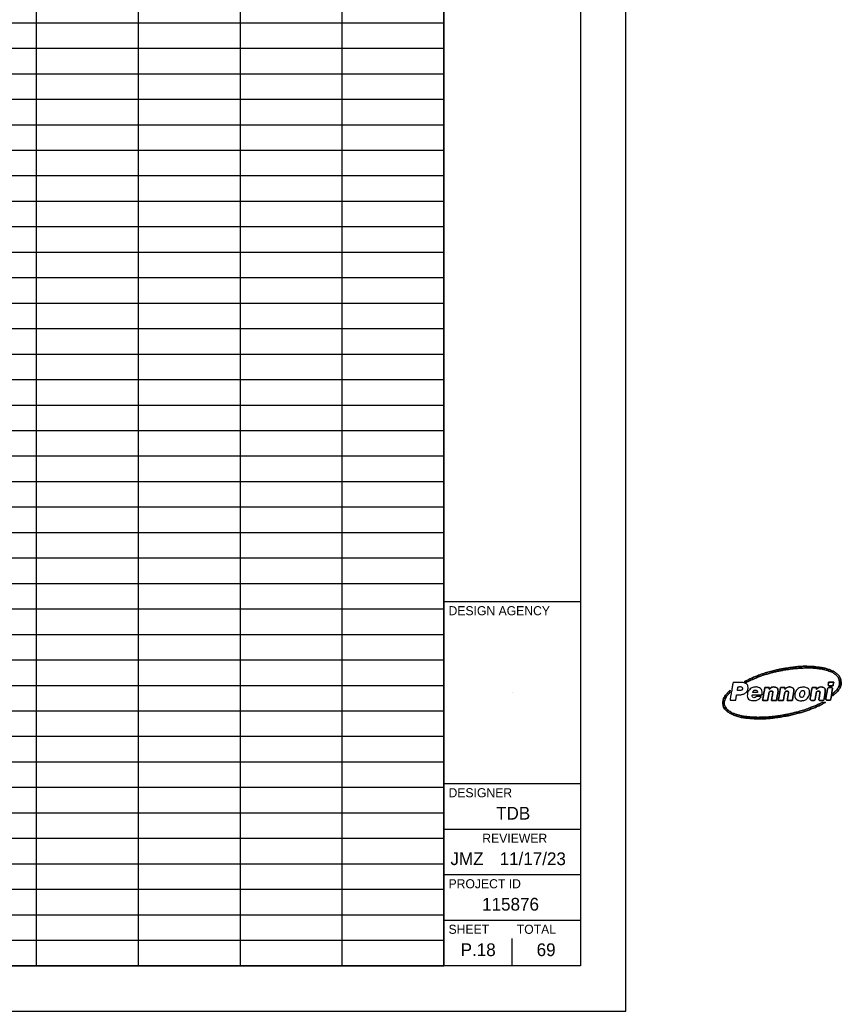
# Model space of a CAD drawing. Extents: x -0.1 to 36.2, y 0 to 22.
# Drawn here: x 27.21 to 36.24, y -0.02 to 10.87 of the extents above; entities that cross this region are included whole.
import ezdxf

# ---------------------------------------------------------------- set-up
doc = ezdxf.new("R2010")
doc.units = 0
for name, color, linetype in [('SH_Border', 7, 'Continuous'), ('SH_Cut_Line', 7, 'Continuous'), ('SH_Data', 7, 'Continuous'), ('SH_Text', 7, 'Continuous')]:
    doc.layers.add(name, color=color, linetype=linetype)

msp = doc.modelspace()

# ---------------------------------------------------------------- linework, layer by layer
at = {"layer": 'SH_Border'}
for p, q in [((31.876, 0.475), (31.876, 21.475)), ((31.876, 4.475), (33.376, 4.475)), ((35.32, 3.478), (35.269, 3.478)), ((31.876, 2.475), (33.376, 2.475)), ((31.876, 1.975), (33.376, 1.975)), ((31.876, 1.475), (33.376, 1.475)), ((31.876, 0.975), (33.376, 0.975))]:
    msp.add_line(p, q, dxfattribs=at)
msp.add_lwpolyline([(1.376, 21.475), (33.376, 21.475), (33.376, 0.475), (1.376, 0.475)], close=True, dxfattribs=at)
for points, degree in [([(35.179, 3.596), (35.186, 3.594), (35.192, 3.591), (35.198, 3.59), (35.2, 3.589), (35.203, 3.589), (35.205, 3.59), (35.233, 3.604), (35.262, 3.618), (35.291, 3.63), (35.332, 3.648), (35.374, 3.663), (35.417, 3.676), (35.459, 3.689), (35.502, 3.7), (35.545, 3.709), (35.584, 3.718), (35.624, 3.726), (35.665, 3.731), (35.697, 3.735), (35.729, 3.739), (35.761, 3.742), (35.786, 3.744), (35.811, 3.745), (35.837, 3.746), (35.892, 3.748), (35.947, 3.745), (36.001, 3.737), (36.031, 3.733), (36.06, 3.727), (36.089, 3.717), (36.124, 3.706), (36.158, 3.692), (36.186, 3.666), (36.201, 3.653), (36.213, 3.636), (36.218, 3.616), (36.223, 3.599), (36.224, 3.582), (36.221, 3.564), (36.218, 3.544), (36.208, 3.527), (36.195, 3.511), (36.183, 3.496), (36.169, 3.483), (36.155, 3.47), (36.153, 3.469), (36.151, 3.467), (36.151, 3.465), (36.15, 3.46), (36.149, 3.454), (36.148, 3.448), (36.147, 3.446), (36.147, 3.444), (36.147, 3.44), (36.171, 3.46), (36.193, 3.48), (36.212, 3.504), (36.221, 3.515), (36.229, 3.528), (36.234, 3.541), (36.24, 3.56), (36.241, 3.579), (36.239, 3.598), (36.235, 3.633), (36.219, 3.66), (36.193, 3.683), (36.169, 3.703), (36.141, 3.716), (36.112, 3.727), (36.075, 3.741), (36.036, 3.749), (35.997, 3.754), (35.962, 3.759), (35.927, 3.762), (35.892, 3.763), (35.836, 3.765), (35.779, 3.762), (35.723, 3.756), (35.692, 3.752), (35.662, 3.748), (35.631, 3.743), (35.585, 3.736), (35.541, 3.727), (35.496, 3.715), (35.436, 3.7), (35.376, 3.682), (35.318, 3.66), (35.277, 3.644), (35.237, 3.626), (35.198, 3.606), (35.192, 3.603), (35.186, 3.6), (35.179, 3.596)], 3), ([(35.179, 3.596), (35.186, 3.6), (35.192, 3.603), (35.198, 3.606), (35.237, 3.626), (35.277, 3.644), (35.318, 3.66), (35.376, 3.682), (35.436, 3.7), (35.496, 3.715), (35.541, 3.727), (35.585, 3.736), (35.631, 3.743), (35.662, 3.748), (35.692, 3.752), (35.723, 3.756), (35.779, 3.762), (35.836, 3.765), (35.892, 3.763), (35.927, 3.762), (35.962, 3.759), (35.997, 3.754), (36.036, 3.749), (36.075, 3.741), (36.112, 3.727), (36.141, 3.716), (36.169, 3.703), (36.193, 3.683), (36.219, 3.66), (36.235, 3.633), (36.239, 3.598), (36.241, 3.579), (36.24, 3.56), (36.234, 3.541), (36.229, 3.528), (36.221, 3.515), (36.212, 3.504), (36.193, 3.48), (36.171, 3.46), (36.147, 3.44), (36.147, 3.444), (36.147, 3.446), (36.148, 3.448), (36.149, 3.454), (36.15, 3.46), (36.151, 3.465), (36.151, 3.467), (36.153, 3.469), (36.155, 3.47), (36.169, 3.483), (36.183, 3.496), (36.195, 3.511), (36.208, 3.527), (36.218, 3.544), (36.221, 3.564), (36.224, 3.582), (36.223, 3.599), (36.218, 3.616), (36.213, 3.636), (36.201, 3.653), (36.186, 3.666), (36.158, 3.692), (36.124, 3.706), (36.089, 3.717), (36.06, 3.727), (36.031, 3.733), (36.001, 3.737), (35.947, 3.745), (35.892, 3.748), (35.837, 3.746), (35.811, 3.745), (35.786, 3.744), (35.761, 3.742), (35.729, 3.739), (35.697, 3.735), (35.665, 3.731), (35.624, 3.726), (35.584, 3.718), (35.545, 3.709), (35.502, 3.7), (35.459, 3.689), (35.417, 3.676), (35.374, 3.663), (35.332, 3.648), (35.291, 3.63), (35.262, 3.618), (35.233, 3.604), (35.205, 3.59), (35.203, 3.589), (35.2, 3.589), (35.198, 3.59), (35.192, 3.591), (35.186, 3.594), (35.179, 3.596)], 3), ([(36.067, 3.367), (36.067, 3.367), (36.067, 3.368), (36.067, 3.368), (36.057, 3.368), (36.047, 3.368), (36.037, 3.368), (36.034, 3.368), (36.032, 3.367), (36.029, 3.366), (35.992, 3.347), (35.954, 3.33), (35.915, 3.315), (35.857, 3.292), (35.798, 3.273), (35.738, 3.258), (35.695, 3.246), (35.651, 3.237), (35.608, 3.229), (35.583, 3.225), (35.558, 3.221), (35.533, 3.218), (35.508, 3.214), (35.482, 3.211), (35.456, 3.209), (35.432, 3.207), (35.408, 3.205), (35.384, 3.205), (35.356, 3.204), (35.327, 3.203), (35.299, 3.205), (35.268, 3.206), (35.237, 3.208), (35.206, 3.211), (35.168, 3.215), (35.131, 3.223), (35.094, 3.234), (35.063, 3.244), (35.033, 3.257), (35.006, 3.277), (34.989, 3.289), (34.975, 3.304), (34.966, 3.323), (34.954, 3.349), (34.955, 3.375), (34.966, 3.402), (34.975, 3.425), (34.989, 3.445), (35.006, 3.463), (35.011, 3.469), (35.017, 3.475), (35.017, 3.484), (35.017, 3.489), (35.019, 3.495), (35.02, 3.501), (35.018, 3.5), (35.018, 3.5), (35.017, 3.499), (35.008, 3.489), (34.998, 3.48), (34.989, 3.469), (34.969, 3.447), (34.953, 3.423), (34.945, 3.394), (34.94, 3.377), (34.939, 3.36), (34.942, 3.343), (34.947, 3.316), (34.961, 3.294), (34.981, 3.276), (35.004, 3.255), (35.03, 3.241), (35.059, 3.229), (35.106, 3.21), (35.155, 3.2), (35.205, 3.194), (35.236, 3.191), (35.267, 3.189), (35.298, 3.187), (35.341, 3.186), (35.383, 3.186), (35.425, 3.19), (35.459, 3.192), (35.494, 3.196), (35.528, 3.2), (35.558, 3.204), (35.589, 3.209), (35.62, 3.214), (35.674, 3.224), (35.728, 3.236), (35.781, 3.252), (35.826, 3.264), (35.87, 3.279), (35.914, 3.296), (35.957, 3.313), (36, 3.331), (36.04, 3.353), (36.049, 3.357), (36.058, 3.362), (36.067, 3.367)], 3), ([(36.067, 3.367), (36.058, 3.362), (36.049, 3.357), (36.04, 3.353), (36, 3.331), (35.957, 3.313), (35.914, 3.296), (35.87, 3.279), (35.826, 3.264), (35.781, 3.252), (35.728, 3.236), (35.674, 3.224), (35.62, 3.214), (35.589, 3.209), (35.558, 3.204), (35.528, 3.2), (35.494, 3.196), (35.459, 3.192), (35.425, 3.19), (35.383, 3.186), (35.341, 3.186), (35.298, 3.187), (35.267, 3.189), (35.236, 3.191), (35.205, 3.194), (35.155, 3.2), (35.106, 3.21), (35.059, 3.229), (35.03, 3.241), (35.004, 3.255), (34.981, 3.276), (34.961, 3.294), (34.947, 3.316), (34.942, 3.343), (34.939, 3.36), (34.94, 3.377), (34.945, 3.394), (34.953, 3.423), (34.969, 3.447), (34.989, 3.469), (34.998, 3.48), (35.008, 3.489), (35.017, 3.499), (35.018, 3.5), (35.018, 3.5), (35.02, 3.501), (35.019, 3.495), (35.017, 3.489), (35.017, 3.484), (35.017, 3.475), (35.011, 3.469), (35.006, 3.463), (34.989, 3.445), (34.975, 3.425), (34.966, 3.402), (34.955, 3.375), (34.954, 3.349), (34.966, 3.323), (34.975, 3.304), (34.989, 3.289), (35.006, 3.277), (35.033, 3.257), (35.063, 3.244), (35.094, 3.234), (35.131, 3.223), (35.168, 3.215), (35.206, 3.211), (35.237, 3.208), (35.268, 3.206), (35.299, 3.205), (35.327, 3.203), (35.356, 3.204), (35.384, 3.205), (35.408, 3.205), (35.432, 3.207), (35.456, 3.209), (35.482, 3.211), (35.508, 3.214), (35.533, 3.218), (35.558, 3.221), (35.583, 3.225), (35.608, 3.229), (35.651, 3.237), (35.695, 3.246), (35.738, 3.258), (35.798, 3.273), (35.857, 3.292), (35.915, 3.315), (35.954, 3.33), (35.992, 3.347), (36.029, 3.366), (36.032, 3.367), (36.034, 3.368), (36.037, 3.368), (36.047, 3.368), (36.057, 3.368), (36.067, 3.368), (36.067, 3.368), (36.067, 3.367), (36.067, 3.367)], 3), ([(35.19, 3.577), (35.178, 3.583), (35.164, 3.585), (35.151, 3.585), (35.119, 3.586), (35.087, 3.585), (35.055, 3.586), (35.053, 3.586), (35.052, 3.585), (35.052, 3.583), (35.048, 3.561), (35.044, 3.54), (35.041, 3.518), (35.035, 3.484), (35.029, 3.449), (35.022, 3.414), (35.021, 3.407), (35.02, 3.399), (35.019, 3.392)], 3), ([(35.092, 3.452), (35.1, 3.452), (35.106, 3.452), (35.113, 3.452), (35.126, 3.452), (35.139, 3.452), (35.152, 3.455), (35.169, 3.458), (35.184, 3.465), (35.196, 3.477), (35.21, 3.493), (35.217, 3.512), (35.217, 3.534), (35.217, 3.553), (35.209, 3.568), (35.19, 3.577)], 3), ([(35.1, 3.497), (35.102, 3.511), (35.105, 3.525), (35.107, 3.538), (35.107, 3.539), (35.109, 3.54), (35.109, 3.54), (35.121, 3.54), (35.132, 3.542), (35.144, 3.538), (35.154, 3.535), (35.158, 3.529), (35.156, 3.518)], 3), ([(35.156, 3.518), (35.153, 3.506), (35.144, 3.498), (35.132, 3.497), (35.121, 3.497), (35.111, 3.497), (35.1, 3.497)], 3), ([(35.372, 3.483), (35.368, 3.508), (35.355, 3.525), (35.331, 3.532), (35.318, 3.537), (35.304, 3.537), (35.291, 3.536), (35.269, 3.533), (35.249, 3.524), (35.234, 3.507), (35.22, 3.493), (35.212, 3.475), (35.21, 3.454), (35.207, 3.425), (35.219, 3.401), (35.248, 3.392), (35.264, 3.387), (35.28, 3.387), (35.297, 3.389), (35.314, 3.391), (35.331, 3.397), (35.344, 3.409), (35.352, 3.416), (35.359, 3.424), (35.363, 3.434)], 3), ([(35.269, 3.478), (35.271, 3.49), (35.28, 3.5), (35.293, 3.502), (35.299, 3.503), (35.305, 3.503), (35.31, 3.5), (35.318, 3.496), (35.321, 3.488), (35.32, 3.478)], 3), ([(35.377, 3.391), (35.378, 3.39), (35.379, 3.39), (35.379, 3.39), (35.396, 3.39), (35.413, 3.39), (35.43, 3.39), (35.433, 3.39), (35.433, 3.392), (35.433, 3.393), (35.435, 3.401), (35.436, 3.41), (35.438, 3.418), (35.441, 3.435), (35.444, 3.453), (35.447, 3.471), (35.449, 3.48), (35.454, 3.488), (35.464, 3.49), (35.477, 3.494), (35.491, 3.491), (35.488, 3.472), (35.487, 3.457), (35.484, 3.443), (35.482, 3.429), (35.479, 3.416), (35.477, 3.404), (35.475, 3.391), (35.476, 3.39), (35.476, 3.39), (35.477, 3.39), (35.494, 3.39), (35.511, 3.39), (35.528, 3.39), (35.53, 3.39), (35.531, 3.392), (35.531, 3.394), (35.535, 3.418), (35.539, 3.441), (35.543, 3.465), (35.546, 3.478), (35.548, 3.49), (35.546, 3.502), (35.544, 3.518), (35.535, 3.53), (35.519, 3.533), (35.497, 3.539), (35.478, 3.535), (35.46, 3.52), (35.457, 3.517), (35.453, 3.513), (35.449, 3.51), (35.45, 3.517), (35.451, 3.524), (35.453, 3.532), (35.436, 3.532), (35.42, 3.532), (35.404, 3.531), (35.403, 3.531), (35.402, 3.53), (35.402, 3.529), (35.401, 3.525), (35.4, 3.521), (35.399, 3.516), (35.394, 3.486), (35.389, 3.455), (35.383, 3.425), (35.381, 3.413), (35.379, 3.402), (35.377, 3.391)], 3), ([(35.377, 3.391), (35.379, 3.402), (35.381, 3.413), (35.383, 3.425), (35.389, 3.455), (35.394, 3.486), (35.399, 3.516), (35.4, 3.521), (35.401, 3.525), (35.402, 3.529), (35.402, 3.53), (35.403, 3.531), (35.404, 3.531), (35.42, 3.532), (35.436, 3.532), (35.453, 3.532), (35.451, 3.524), (35.45, 3.517), (35.449, 3.51), (35.453, 3.513), (35.457, 3.517), (35.46, 3.52), (35.478, 3.535), (35.497, 3.539), (35.519, 3.533), (35.535, 3.53), (35.544, 3.518), (35.546, 3.502), (35.548, 3.49), (35.546, 3.478), (35.543, 3.465), (35.539, 3.441), (35.535, 3.418), (35.531, 3.394), (35.531, 3.392), (35.53, 3.39), (35.528, 3.39), (35.511, 3.39), (35.494, 3.39), (35.477, 3.39), (35.476, 3.39), (35.476, 3.39), (35.475, 3.391), (35.477, 3.404), (35.479, 3.416), (35.482, 3.429), (35.484, 3.443), (35.487, 3.457), (35.488, 3.472), (35.491, 3.491), (35.477, 3.494), (35.464, 3.49), (35.454, 3.488), (35.449, 3.48), (35.447, 3.471), (35.444, 3.453), (35.441, 3.435), (35.438, 3.418), (35.436, 3.41), (35.435, 3.401), (35.433, 3.393), (35.433, 3.392), (35.433, 3.39), (35.43, 3.39), (35.413, 3.39), (35.396, 3.39), (35.379, 3.39), (35.379, 3.39), (35.378, 3.39), (35.377, 3.391)], 3), ([(35.55, 3.391), (35.551, 3.39), (35.551, 3.39), (35.551, 3.39), (35.569, 3.39), (35.586, 3.39), (35.604, 3.39), (35.605, 3.39), (35.606, 3.392), (35.606, 3.393), (35.609, 3.41), (35.612, 3.427), (35.615, 3.444), (35.617, 3.454), (35.619, 3.465), (35.622, 3.475), (35.626, 3.488), (35.638, 3.494), (35.651, 3.491), (35.657, 3.49), (35.66, 3.486), (35.661, 3.48), (35.662, 3.477), (35.662, 3.474), (35.661, 3.471), (35.66, 3.46), (35.658, 3.448), (35.656, 3.437), (35.653, 3.422), (35.651, 3.406), (35.648, 3.391), (35.648, 3.391), (35.648, 3.39), (35.649, 3.39), (35.666, 3.39), (35.684, 3.39), (35.701, 3.39), (35.702, 3.39), (35.704, 3.392), (35.704, 3.393), (35.708, 3.416), (35.712, 3.438), (35.716, 3.46), (35.718, 3.472), (35.719, 3.484), (35.72, 3.497), (35.72, 3.512), (35.714, 3.525), (35.698, 3.531), (35.677, 3.539), (35.658, 3.537), (35.639, 3.525), (35.633, 3.52), (35.628, 3.515), (35.622, 3.51), (35.623, 3.518), (35.625, 3.524), (35.626, 3.532), (35.609, 3.532), (35.593, 3.532), (35.577, 3.532), (35.575, 3.532), (35.575, 3.53), (35.574, 3.528), (35.57, 3.504), (35.566, 3.48), (35.562, 3.457), (35.558, 3.435), (35.554, 3.413), (35.55, 3.391)], 3), ([(35.55, 3.391), (35.554, 3.413), (35.558, 3.435), (35.562, 3.457), (35.566, 3.48), (35.57, 3.504), (35.574, 3.528), (35.575, 3.53), (35.575, 3.532), (35.577, 3.532), (35.593, 3.532), (35.609, 3.532), (35.626, 3.532), (35.625, 3.524), (35.623, 3.518), (35.622, 3.51), (35.628, 3.515), (35.633, 3.52), (35.639, 3.525), (35.658, 3.537), (35.677, 3.539), (35.698, 3.531), (35.714, 3.525), (35.72, 3.512), (35.72, 3.497), (35.719, 3.484), (35.718, 3.472), (35.716, 3.46), (35.712, 3.438), (35.708, 3.416), (35.704, 3.393), (35.704, 3.392), (35.702, 3.39), (35.701, 3.39), (35.684, 3.39), (35.666, 3.39), (35.649, 3.39), (35.648, 3.39), (35.648, 3.391), (35.648, 3.391), (35.651, 3.406), (35.653, 3.422), (35.656, 3.437), (35.658, 3.448), (35.66, 3.46), (35.661, 3.471), (35.662, 3.474), (35.662, 3.477), (35.661, 3.48), (35.66, 3.486), (35.657, 3.49), (35.651, 3.491), (35.638, 3.494), (35.626, 3.488), (35.622, 3.475), (35.619, 3.465), (35.617, 3.454), (35.615, 3.444), (35.612, 3.427), (35.609, 3.41), (35.606, 3.393), (35.606, 3.392), (35.605, 3.39), (35.604, 3.39), (35.586, 3.39), (35.569, 3.39), (35.551, 3.39), (35.551, 3.39), (35.551, 3.39), (35.55, 3.391)], 3), ([(35.893, 3.483), (35.892, 3.505), (35.881, 3.521), (35.861, 3.529), (35.841, 3.537), (35.821, 3.537), (35.801, 3.533), (35.777, 3.528), (35.758, 3.516), (35.745, 3.495), (35.744, 3.493), (35.743, 3.49), (35.742, 3.488), (35.74, 3.486), (35.739, 3.484), (35.738, 3.482), (35.734, 3.471), (35.731, 3.459), (35.731, 3.447), (35.731, 3.445), (35.731, 3.442), (35.731, 3.44), (35.731, 3.432), (35.733, 3.425), (35.735, 3.419), (35.736, 3.418), (35.736, 3.416), (35.737, 3.415), (35.738, 3.414), (35.738, 3.413), (35.739, 3.412), (35.741, 3.409), (35.744, 3.405), (35.747, 3.402), (35.749, 3.401), (35.751, 3.399), (35.754, 3.398), (35.754, 3.397), (35.755, 3.397), (35.755, 3.397), (35.756, 3.396), (35.758, 3.395), (35.759, 3.395), (35.761, 3.394), (35.763, 3.393), (35.765, 3.392), (35.776, 3.388), (35.787, 3.386), (35.799, 3.386)], 3), ([(35.786, 3.446), (35.787, 3.463), (35.79, 3.476), (35.799, 3.488), (35.804, 3.494), (35.811, 3.498), (35.819, 3.498), (35.828, 3.498), (35.833, 3.495), (35.836, 3.486), (35.837, 3.48), (35.838, 3.473), (35.837, 3.466)], 3), ([(35.921, 3.531), (35.913, 3.484), (35.905, 3.438), (35.897, 3.39), (35.915, 3.39), (35.934, 3.39), (35.952, 3.39), (35.955, 3.405), (35.957, 3.419), (35.959, 3.433), (35.962, 3.446), (35.964, 3.459), (35.967, 3.471), (35.97, 3.485), (35.98, 3.492), (35.993, 3.492), (36.002, 3.491), (36.007, 3.487), (36.008, 3.478), (36.008, 3.475), (36.008, 3.472), (36.007, 3.469), (36.004, 3.45), (36.001, 3.431), (35.998, 3.412), (35.996, 3.405), (35.995, 3.398), (35.994, 3.39), (36.013, 3.39), (36.031, 3.39), (36.049, 3.39), (36.05, 3.392), (36.05, 3.393), (36.05, 3.394), (36.054, 3.415), (36.058, 3.437), (36.061, 3.458), (36.064, 3.472), (36.067, 3.485), (36.066, 3.5), (36.064, 3.516), (36.056, 3.528), (36.04, 3.533), (36.015, 3.54), (35.993, 3.534), (35.975, 3.516), (35.973, 3.514), (35.971, 3.512), (35.969, 3.51), (35.969, 3.51), (35.968, 3.51), (35.968, 3.511), (35.969, 3.517), (35.971, 3.524), (35.972, 3.531), (35.955, 3.531), (35.938, 3.531), (35.921, 3.531)], 3), ([(35.921, 3.531), (35.938, 3.531), (35.955, 3.531), (35.972, 3.531), (35.971, 3.524), (35.969, 3.517), (35.968, 3.511), (35.968, 3.51), (35.969, 3.51), (35.969, 3.51), (35.971, 3.512), (35.973, 3.514), (35.975, 3.516), (35.993, 3.534), (36.015, 3.54), (36.04, 3.533), (36.056, 3.528), (36.064, 3.516), (36.066, 3.5), (36.067, 3.485), (36.064, 3.472), (36.061, 3.458), (36.058, 3.437), (36.054, 3.415), (36.05, 3.394), (36.05, 3.393), (36.05, 3.392), (36.049, 3.39), (36.031, 3.39), (36.013, 3.39), (35.994, 3.39), (35.995, 3.398), (35.996, 3.405), (35.998, 3.412), (36.001, 3.431), (36.004, 3.45), (36.007, 3.469), (36.008, 3.472), (36.008, 3.475), (36.008, 3.478), (36.007, 3.487), (36.002, 3.491), (35.993, 3.492), (35.98, 3.492), (35.97, 3.485), (35.967, 3.471), (35.964, 3.459), (35.962, 3.446), (35.959, 3.433), (35.957, 3.419), (35.955, 3.405), (35.952, 3.39), (35.934, 3.39), (35.915, 3.39), (35.897, 3.39), (35.905, 3.438), (35.913, 3.484), (35.921, 3.531)], 3), ([(36.124, 3.392), (36.106, 3.392), (36.087, 3.392), (36.069, 3.392), (36.077, 3.439), (36.085, 3.485), (36.093, 3.532), (36.112, 3.532), (36.13, 3.532), (36.148, 3.532), (36.14, 3.485), (36.132, 3.439), (36.124, 3.392)], 3), ([(36.124, 3.392), (36.132, 3.439), (36.14, 3.485), (36.148, 3.532), (36.13, 3.532), (36.112, 3.532), (36.093, 3.532), (36.085, 3.485), (36.077, 3.439), (36.069, 3.392), (36.087, 3.392), (36.106, 3.392), (36.124, 3.392)], 3), ([(36.159, 3.59), (36.156, 3.578), (36.154, 3.566), (36.152, 3.553), (36.152, 3.553), (36.15, 3.551), (36.149, 3.551), (36.132, 3.551), (36.115, 3.551), (36.097, 3.551), (36.098, 3.561), (36.1, 3.57), (36.101, 3.579), (36.102, 3.581), (36.103, 3.584), (36.103, 3.586), (36.103, 3.59), (36.104, 3.591), (36.108, 3.591), (36.123, 3.59), (36.139, 3.59), (36.154, 3.59), (36.156, 3.59), (36.157, 3.59), (36.159, 3.59)], 3), ([(36.159, 3.59), (36.157, 3.59), (36.156, 3.59), (36.154, 3.59), (36.139, 3.59), (36.123, 3.59), (36.108, 3.591), (36.104, 3.591), (36.103, 3.59), (36.103, 3.586), (36.103, 3.584), (36.102, 3.581), (36.101, 3.579), (36.1, 3.57), (36.098, 3.561), (36.097, 3.551), (36.115, 3.551), (36.132, 3.551), (36.149, 3.551), (36.15, 3.551), (36.152, 3.553), (36.152, 3.553), (36.154, 3.566), (36.156, 3.578), (36.159, 3.59)], 3), ([(35.019, 3.392), (35.02, 3.392), (35.02, 3.392), (35.021, 3.392), (35.04, 3.392), (35.06, 3.392), (35.079, 3.392), (35.081, 3.392), (35.082, 3.393), (35.082, 3.395), (35.084, 3.406), (35.086, 3.417), (35.088, 3.429), (35.089, 3.437), (35.091, 3.444), (35.092, 3.452)], 3), ([(35.363, 3.434), (35.346, 3.434), (35.329, 3.434), (35.312, 3.434), (35.311, 3.434), (35.31, 3.433), (35.309, 3.432), (35.305, 3.429), (35.301, 3.425), (35.296, 3.423), (35.28, 3.417), (35.263, 3.426), (35.264, 3.445), (35.264, 3.449), (35.265, 3.45), (35.269, 3.45), (35.301, 3.45), (35.333, 3.45), (35.365, 3.45), (35.367, 3.45), (35.369, 3.45), (35.37, 3.45)], 3), ([(35.37, 3.45), (35.373, 3.461), (35.373, 3.472), (35.372, 3.483)], 2), ([(35.837, 3.466), (35.837, 3.456), (35.834, 3.446), (35.828, 3.437), (35.823, 3.427), (35.813, 3.422), (35.802, 3.424), (35.796, 3.425), (35.791, 3.428), (35.789, 3.435), (35.788, 3.439), (35.787, 3.444), (35.786, 3.446)], 3), ([(35.799, 3.386), (35.806, 3.386), (35.814, 3.387), (35.821, 3.388), (35.84, 3.392), (35.857, 3.4), (35.87, 3.414), (35.887, 3.434), (35.895, 3.457), (35.893, 3.483)], 3)]:
    msp.add_open_spline(points, degree=degree, dxfattribs=at)
at = {"layer": 'SH_Cut_Line'}
msp.add_lwpolyline([(-0.124, -0.025), (33.876, -0.025), (33.876, 21.975), (-0.124, 21.975)], close=True, dxfattribs=at)
at = {"layer": 'SH_Data'}
for p, q in [((32.626, 3.475), (32.626, 3.475)), ((32.626, 0.475), (32.626, 0.775)), ((32.251, 0.65), (32.251, 0.65))]:
    msp.add_line(p, q, dxfattribs=at)
at = {"layer": 'SH_Text'}
for p, q in [((27.394, 21.475), (27.394, 0.475)), ((28.514, 21.475), (28.514, 0.475)), ((29.635, 21.475), (29.635, 0.475)), ((30.755, 21.475), (30.755, 0.475)), ((31.876, 21.475), (31.876, 0.475)), ((1.376, 10.835), (31.876, 10.835)), ((1.376, 10.555), (31.876, 10.555)), ((1.376, 10.275), (31.876, 10.275)), ((1.376, 9.995), (31.876, 9.995)), ((1.376, 9.715), (31.876, 9.715)), ((1.376, 9.435), (31.876, 9.435)), ((1.376, 9.155), (31.876, 9.155)), ((1.376, 8.875), (31.876, 8.875)), ((1.376, 8.595), (31.876, 8.595)), ((1.376, 8.315), (31.876, 8.315)), ((1.376, 8.035), (31.876, 8.035)), ((1.376, 7.755), (31.876, 7.755)), ((1.376, 7.475), (31.876, 7.475)), ((1.376, 7.195), (31.876, 7.195)), ((1.376, 6.915), (31.876, 6.915)), ((1.376, 6.635), (31.876, 6.635)), ((1.376, 6.355), (31.876, 6.355)), ((1.376, 6.075), (31.876, 6.075)), ((1.376, 5.795), (31.876, 5.795)), ((1.376, 5.515), (31.876, 5.515)), ((1.376, 5.235), (31.876, 5.235)), ((1.376, 4.955), (31.876, 4.955)), ((1.376, 4.675), (31.876, 4.675)), ((1.376, 4.395), (31.876, 4.395)), ((1.376, 4.115), (31.876, 4.115)), ((1.376, 3.835), (31.876, 3.835)), ((1.376, 3.555), (31.876, 3.555)), ((1.376, 3.275), (31.876, 3.275)), ((1.376, 2.995), (31.876, 2.995)), ((1.376, 2.715), (31.876, 2.715)), ((1.376, 2.435), (31.876, 2.435)), ((1.376, 2.155), (31.876, 2.155)), ((1.376, 1.875), (31.876, 1.875)), ((1.376, 1.595), (31.876, 1.595)), ((1.376, 1.315), (31.876, 1.315)), ((1.376, 1.035), (31.876, 1.035)), ((1.376, 0.755), (31.876, 0.755)), ((1.376, 0.475), (31.876, 0.475))]:
    msp.add_line(p, q, dxfattribs=at)

# ---------------------------------------------------------------- texts
at = {"layer": 'SH_Data'}
for s, height, p in [('DESIGN AGENCY', 0.1, (31.926, 4.325)), ('DESIGNER', 0.1, (31.926, 2.325)), ('TDB', 0.14, (32.449, 2.08)), ('REVIEWER', 0.1, (32.297, 1.825)), ('JMZ', 0.14, (31.947, 1.58)), ('11/17/23', 0.14, (32.487, 1.58)), ('PROJECT ID', 0.1, (31.926, 1.325)), ('115876', 0.14, (32.295, 1.08)), ('SHEET', 0.1, (31.926, 0.825)), ('TOTAL', 0.1, (32.676, 0.825)), ('P.18', 0.14, (32.059, 0.58)), ('69', 0.14, (32.894, 0.58))]:
    msp.add_text(s, height=height, dxfattribs=at).set_placement(p)

doc.saveas('drawing.dxf')
